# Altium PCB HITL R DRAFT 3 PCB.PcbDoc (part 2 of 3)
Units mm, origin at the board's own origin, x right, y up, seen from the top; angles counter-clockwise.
Board outline 90 x 65 mm, 6 copper layers (L1, L2, L3, L4, L5, L6), stack 1.752 mm thick; 198 components, 194 nets, 830 pads, 458 vias.
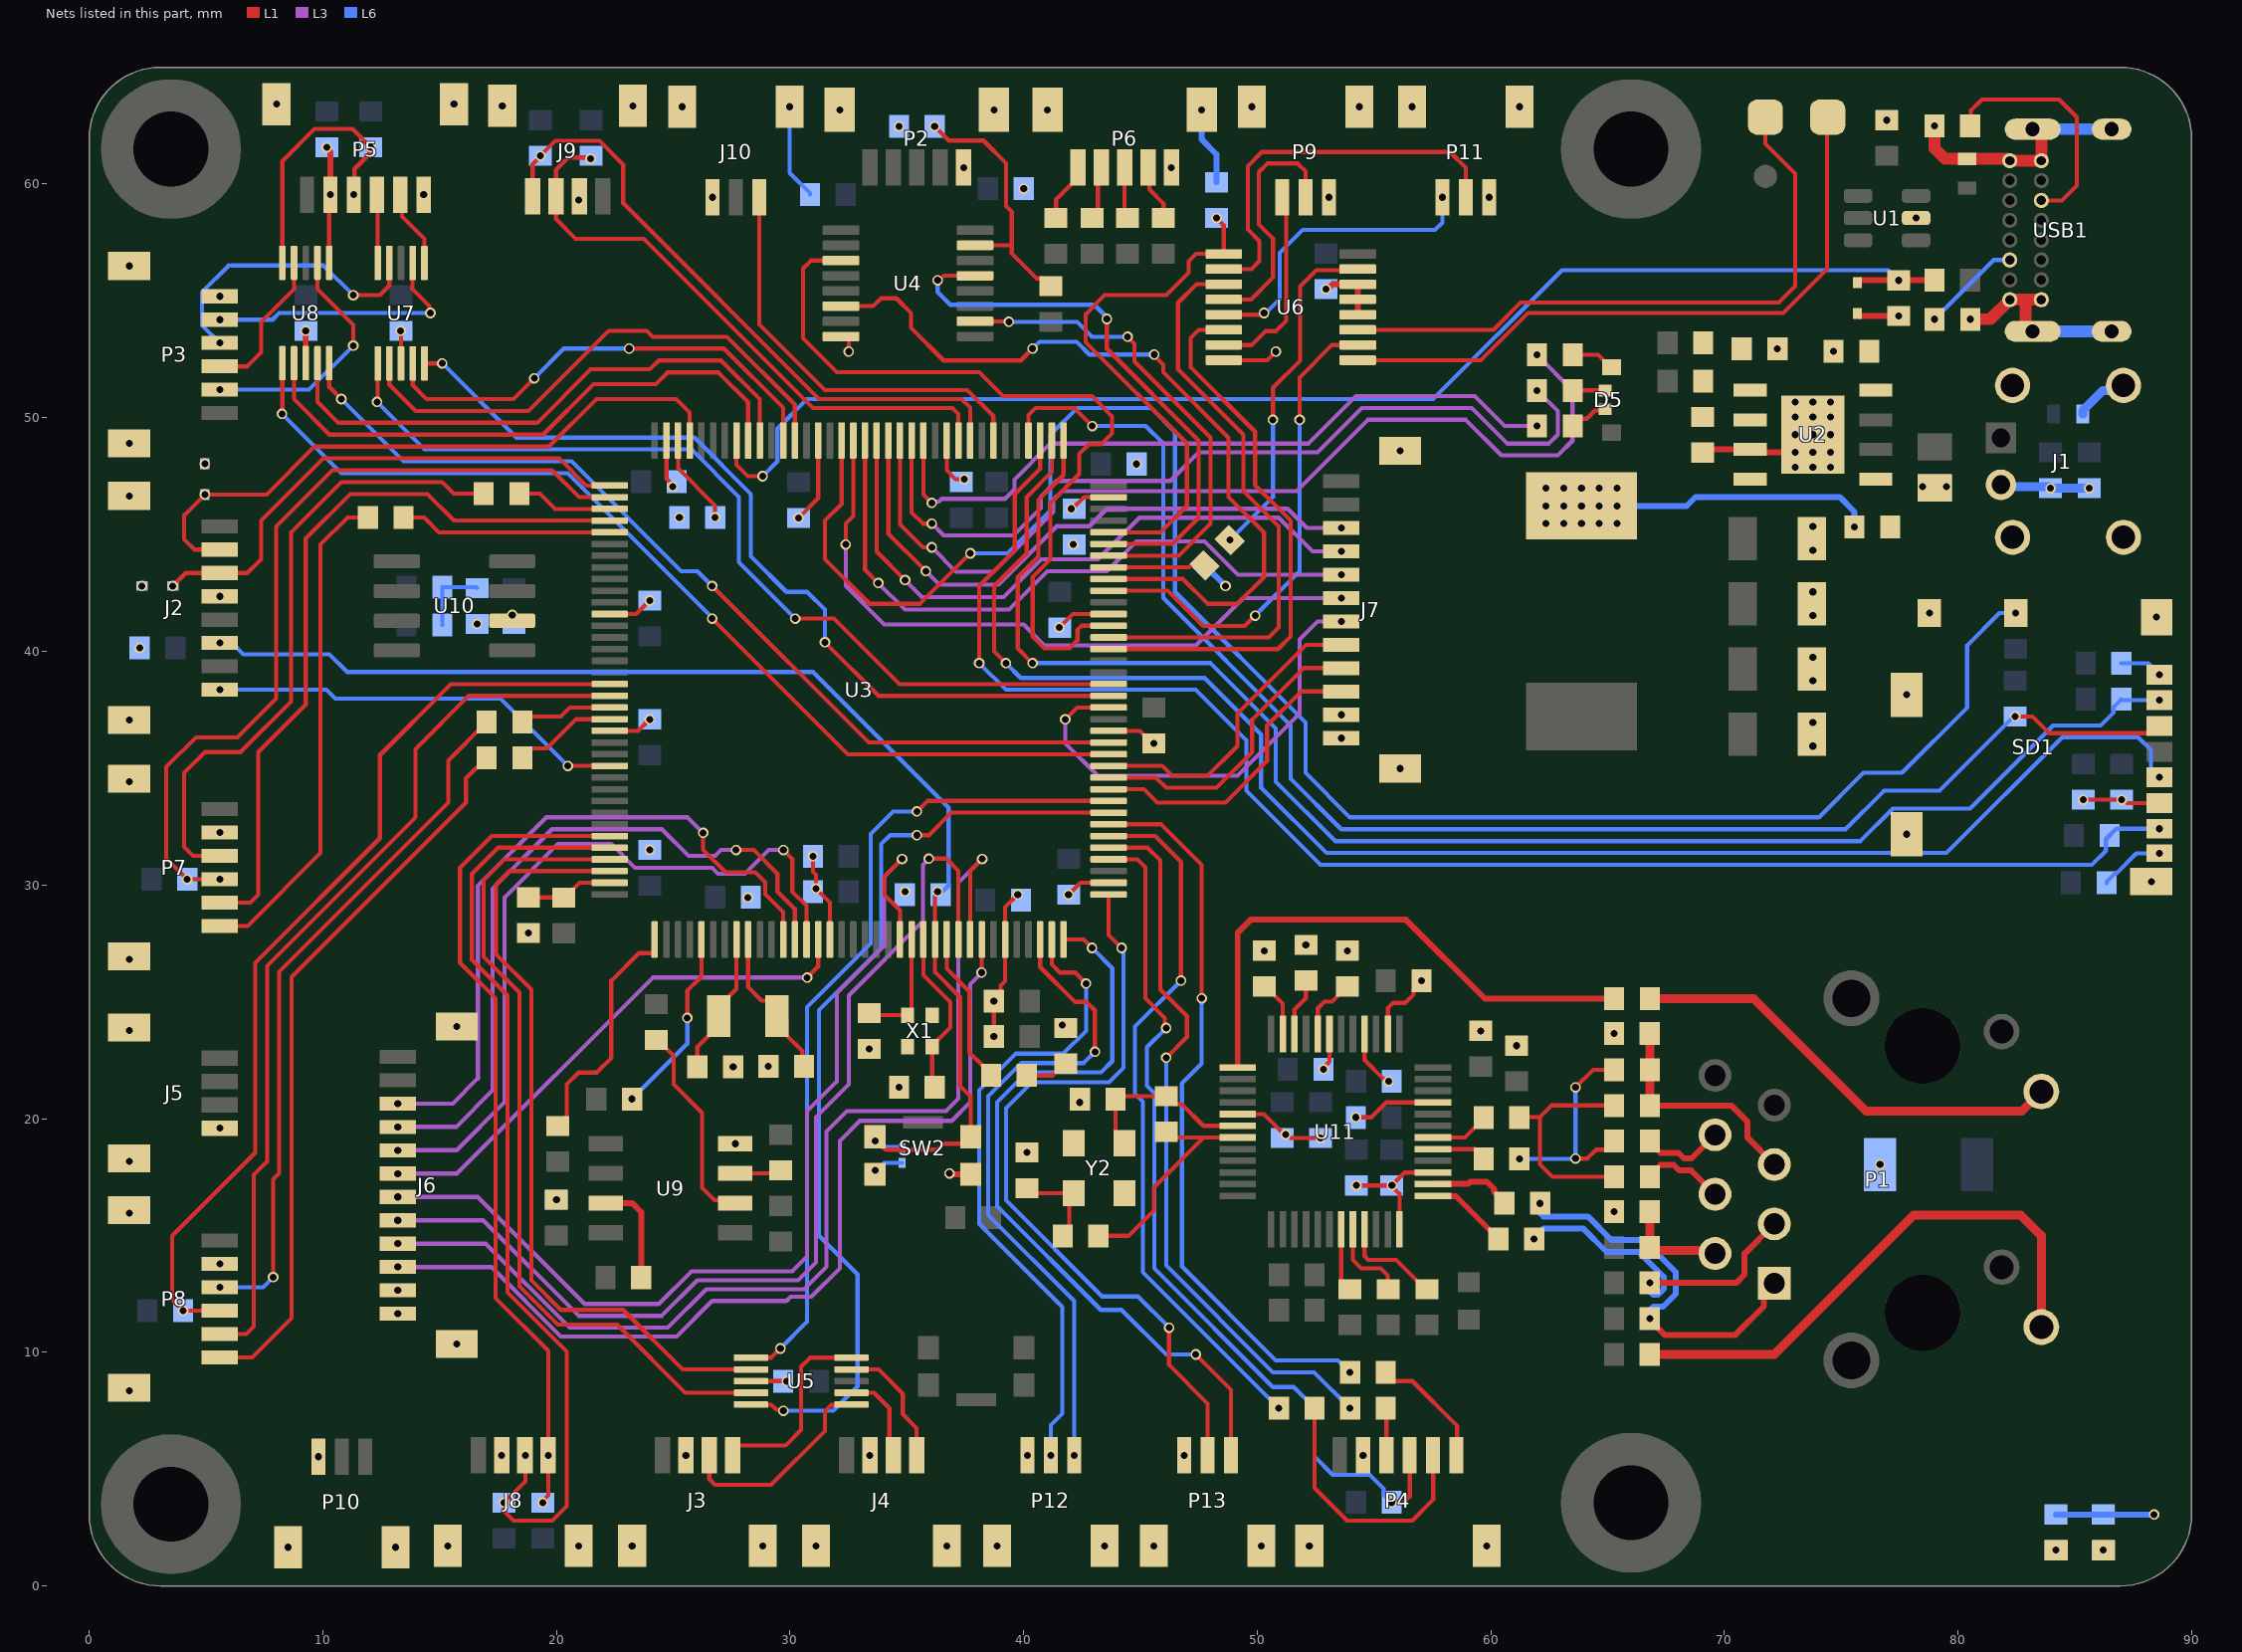
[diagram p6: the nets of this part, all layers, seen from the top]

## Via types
v1: diameter 0.451, hole 0.301, L1 to L6, 453 vias
v2: diameter 0.45, hole 0.3, L1 to L6, 5 vias

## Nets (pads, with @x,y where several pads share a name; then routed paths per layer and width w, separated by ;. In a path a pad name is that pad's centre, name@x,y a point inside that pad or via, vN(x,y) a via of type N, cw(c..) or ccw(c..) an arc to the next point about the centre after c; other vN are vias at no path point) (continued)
GND: C1.1 C2.1 C3.2 C5.1 C6.1 C8.1 C9.1 C10.1 C11.1 C12.1 C13.1 C14.1 C15.1 C16.1 C17.1 C18.1 C19.1 C20.1 C21.1 C22.1 C23.1 C24.1 C25.1 C27.1 C28.1 C29.1 C30.1 C31.1 C32.1 C33.1 C34.1 C35.1 C36.1 C37.2 C38.2 C39.1 C40.1 C41.1 C42.1 C43.1 C44.1 C45.1 C46.1 C47.1 C51.1 C52.1 C53.1 C54.1 C55.1 C56.1 C57.1 C60.1 C61.1 C62.1 C63.1 C64.1 C65.1 C66.1 C67.1 C68.1 D1.2 D2.2 D3.2 D4.2 D6.1 D7.1 J1.2 J1.SH1 J1.SH2 J1.SH3 J1.SH4 J2.4 J2.P1 J2.P2 J3.2 J3.S1 J3.S2 J4.2 J4.S1 J4.S2 J5.4 J5.S1 J5.S2 J6.11 J6.12 J6.S1 J6.S2 J7.11 J7.12 J7.S1 J7.S2 J8.2 J8.S1 J8.S2 J9.2 J9.S1 J9.S2 J10.3 J10.S1 J10.S2 P2.5 P2.6 P2.7 P3.1 P3.S1 P3.S2 P4.2 P4.S1 P4.S2 P5.1 P5.S1 P5.S2 P6.5 P6.6 P6.7 P7.2 P7.S1 P7.S2 P8.2 P8.S1 P8.S2 P9.1 P9.S1 P9.S2 P10.1 P10.S1 P10.S2 P11.1 P11.S1 P11.S2 P12.1 P12.S1 P12.S2 P13.1 P13.S1 P13.S2 R2.1 R3.1 R4.1 R6.1 R7.1 R8.2 R13.2 R18.1 R21.1 R22.1 R23.1 R24.1 R58.1 R59.1 R77.1 R78.1 SD1.6 SD1.10 SD1.G1 SD1.G2 SD1.G3 SD1.G4 SW2.2 SW2.3 U1.2 U2.7 U2.9 U3.16 U3.31 U3.38 U3.51 U3.61 U3.83 U3.94 U3.107 U3.120 U3.130 U4.8 U5.3 U6.8 U6.12 U6.13 U6.14 U7.3 U8.3 U9.4 U10.2 U11.3 U11.9 U11.14 U11.16 U11.19 U11.29 U11.48 USB1.A1 USB1.A12 USB1.B1 USB1.B12 USB1.S1 USB1.S2 USB1.S3 USB1.S4 X1.2 X1.4 Y2.2 Y2.4 | length 108.8
  L1 w0.178: v1(13.335,53.721) 13.343,53.713 13.343,52.332 U7.3@13.351,52.324 ; U3.130@22.279,36.596 23.495,36.596 v1(23.99,37.091) ; U3.120@22.279,41.596 23.415,41.596 v1(23.99,42.171) ; U3.107@24.709,49.026 24.709,47.399 24.976,47.132 v1(24.976,47.058) ; U5.3@28.332,8.761 29.856,8.761 v1(29.858,8.759) ; v1(30.366,45.713) 31.209,46.556 U3.94@31.209,49.026 ; v1(30.981,31.229) 30.981,30.565 31.115,30.431 v1(31.115,29.845) 31.709,29.251 U3.16@31.709,27.666 ; U4.8@32.182,53.478 32.396,53.478 32.512,53.362 v1(32.512,52.832) ; U3.83@36.709,49.026 36.709,47.746 37.084,47.371 v1(37.465,47.371) ; v1(38.728,23.508) v1(38.728,25.032) 39.018,25.322 39.018,25.683 39.209,25.874 39.209,29.049 v1(39.751,29.591) ; v1(41.529,41.021) 42.104,41.596 U3.61@43.639,41.596 ; v1(41.923,29.584) 42.435,30.096 U3.38@43.639,30.096 ; U3.51@43.639,36.596 44.985,36.596 45.52,36.061 v1(45.58,36.061) ; U6.8@48.568,52.459 50.427,52.459 v1(50.8,52.832) ; U11.29@49.164,20.192 50.277,20.192 51.152,19.317 51.289,19.317 51.436,19.17 v1(52.718,19.17) ; v1(52.839,22.111) 52.839,22.185 53.094,22.44 U11.19@53.094,23.622 ; v1(54.222,20.053) 54.88,20.053 55.519,20.692 U11.9@57.524,20.692 ; v1(54.242,17.138) v1(55.766,17.138) ; U11.16@54.594,23.622 54.594,22.513 55.402,21.706 55.437,21.706 55.552,21.59 v1(55.626,21.59) ; U11.14@55.594,23.622 55.594,24.733 55.814,24.953 56.333,24.953 56.689,25.308 56.689,25.554 v1(57.03,25.895) ; U11.48@56.094,15.262 56.094,16.771 55.766,17.099 v1(55.766,17.138) ; U11.3@57.524,17.692 56.32,17.692 v1(55.766,17.138) ; v1(85.357,33.648) v1(87.008,33.648) 87.082,33.648 87.224,33.506 SD1.6@88.624,33.506
  L1 w0.254: U8.3@9.271,52.333 v1(9.271,53.721) ; v1(36.83,17.653) 36.883,17.653 36.921,17.615 SW2.3@37.737,17.615 ; v1(52.946,55.5) 53.02,55.5 53.232,55.712 U6.14@54.305,55.712 U6.13@54.305,55.062 U6.12@54.305,54.412 ; C12.1@69.075,48.507 69.209,48.641 U2.7@71.095,48.641 71.222,48.514 v1(73.025,48.514) ; D3.2@75.692,54.458 75.692,54.422 75.765,54.349 v1(77.457,54.349)
  L1 w0.508: v1(78.987,62.497) 78.987,61.541 79.451,61.077 D1.2@80.391,61.077 82.103,61.077 82.178,61.002 USB1.B1@83.566,61.002 83.566,62.018 83.232,62.352 USB1.S4@83.196,62.352 ; v1(80.525,54.216) 81.38,54.216 USB1.A1@82.216,55.052 82.891,55.052 ; USB1.S3@83.196,53.702 82.891,54.007 82.891,55.052 ; USB1.B12@83.566,55.052 82.891,55.052
  L6 w0.178: v1(29.986,63.311) 29.986,60.478 30.854,59.61 R21.1@30.854,59.55 ; v1(33.655,17.78) 33.705,17.78 34.028,18.103 D4.2@34.798,18.103
  L6 w0.254: v1(47.623,63.182) 47.623,61.908 48.26,61.271 R24.1@48.26,60.077 ; R23.1@47.741,43.68 47.76,43.68 v1(48.641,42.799) ; R77.1@84.188,3.055 R78.1@86.22,3.055 86.227,3.048 v2(88.392,3.048)
  L6 w0.381: J1.2@81.834,47.133 81.909,47.058 83.885,47.058 v1(83.96,46.983) v1(85.611,46.983) ; D2.2@85.334,50.165 85.334,50.29 86.211,51.167 86.868,51.167 J1.SH4@87.084,51.383
  L6 w0.508: USB1.S3@83.196,53.702 USB1.S1@86.576,53.702 ; USB1.S4@83.196,62.352 USB1.S2@86.576,62.352
  other v1: 8.509,1.651 13.109,1.651 15.353,1.713 20.953,1.713 23.243,1.713 28.843,1.713 31.117,1.713 36.717,1.713 38.864,1.713 43.464,1.713 45.579,1.713 50.179,1.713 52.231,1.713 59.831,1.713 9.809,5.526 17.653,5.588 25.543,5.588 33.417,5.588 40.164,5.588 46.879,5.588 54.531,5.588 1.713,8.352 15.736,10.345 13.211,11.645 13.211,12.645 5.588,13.779 1.713,15.952 65.271,16.015 20.005,16.528 76.662,18.034 1.713,18.163 40.145,18.549 27.662,18.923 51.215,19.317 5.588,19.59 42.41,20.693 34.664,21.349 27.566,22.212 29.076,22.238 33.388,22.98 61.1,23.121 65.271,23.635 1.713,23.763 59.576,23.756 15.736,23.945 41.656,24.003 1.713,26.815 50.305,27.185 53.861,27.185 52.083,27.439 18.809,27.941 28.194,29.464 34.925,29.718 88.274,30.146 23.99,31.503 77.799,32.171 5.588,32.242 1.713,34.415 56.122,34.983 73.787,35.941 53.597,36.283 73.787,36.957 1.713,37.054 53.597,37.283 77.799,38.141 73.787,38.735 73.787,39.751 2.16,40.145 16.6,41.175 88.499,41.466 73.787,41.529 18.11,41.563 78.774,41.641 5.588,42.354 73.787,42.545 2.261,42.799 73.787,44.323 42.125,44.577 73.787,45.339 25.266,45.733 1.713,46.654 78.486,47.046 79.502,47.046 73.025,47.879 73.787,47.879 74.549,47.879 4.953,48.031 44.838,48.019 73.787,48.514 74.549,48.514 56.122,48.583 1.713,48.897 73.025,49.276 73.787,49.276 74.549,49.276 73.025,50.038 73.787,50.038 74.549,50.038 73.025,50.673 73.787,50.673 74.549,50.673 74.669,52.845 72.27,52.946 5.588,55.197 1.713,56.497 78.207,58.547 20.955,59.309 26.686,59.436 53.07,59.436 59.927,59.436 14.318,59.548 40.004,59.804 37.433,60.712 46.323,60.712 34.664,62.471 76.949,62.737 32.133,63.182 38.733,63.182 41.023,63.182 25.386,63.311 49.77,63.311 54.37,63.311 56.627,63.311 61.227,63.311 17.684,63.347 23.284,63.347 8.018,63.423 15.618,63.423
GPS_RX_IN: P3.2 U7.7 | length 11.9
  L1 w0.178: U7.7@13.837,56.885 13.837,55.505 14.562,54.78 14.562,54.526 v1(14.605,54.483)
  L6 w0.178: v1(5.588,54.197) 7.842,54.197 8.128,54.483 v1(14.605,54.483)
GPS_RX_OUT: P5.2 U7.6 | length 3.4
  L1 w0.178: P5.2@13.318,59.548 13.399,59.466 13.399,58.61 14.351,57.658 U7.6@14.351,56.624
GPS_RX_SEL: U3.54 U7.5 | length 37.6
  L1 w0.178: U7.5@14.351,52.324 v1(15.113,52.324) ; v1(31.496,40.386) 33.786,38.096 U3.54@43.639,38.096
  L6 w0.178: v1(15.113,52.324) 18.288,49.149 25.908,49.149 28.321,46.736 28.321,44.069 29.845,42.545 30.734,42.545 31.496,41.783 v1(31.496,40.386)
GPS_TX_IN: P3.3 U7.9 | length 12.5
  L1 w0.178: v1(11.303,55.245) 12.446,55.245 12.851,55.65 U7.9@12.851,56.624
  L6 w0.178: v1(5.588,53.197) 4.826,53.959 4.826,55.372 5.969,56.515 ; 6.096,56.515 10.033,56.515 v1(11.303,55.245)
GPS_TX_OUT: P5.3 U7.10 | length 2.9
  L1 w0.178: P5.3@12.318,59.548 12.351,59.514 U7.10@12.351,56.624
GPS_TX_SEL: U3.55 U7.1 | length 39.6
  L1 w0.178: v1(12.319,50.673) 12.351,50.705 U7.1@12.351,52.324 ; v1(30.226,41.402) 31.877,41.402 34.683,38.596 U3.55@43.639,38.596
  L6 w0.178: v1(12.319,50.673) 14.351,48.641 25.781,48.641 27.813,46.609 27.813,43.815 v1(30.226,41.402)
HITL2PDB_GPIO: U3.63 U6.10 | length 21.1
  L1 w0.178: U3.63@43.639,42.596 46.177,42.596 47.692,41.081 49.463,41.081 v1(49.911,41.529) ; v1(51.816,49.911) 51.816,51.723 53.205,53.112 U6.10@54.305,53.112
  L6 w0.178: v1(49.911,41.529) 51.816,43.434 v1(51.816,49.911)
HITL_DSHOT1: U3.60 U4.3 | length 34.6
  L1 w0.178: U4.3@32.182,56.728 30.893,56.728 30.553,56.388 30.553,53.394 32.004,51.943 38.1,51.943 39.116,50.927 42.926,50.927 43.792,50.061 43.792,49.335 43.318,48.861 42.797,48.861 42.385,48.448 42.385,47.592 41.148,46.355 41.148,43.942 40.386,43.18 40.386,40.64 40.894,40.132 41.962,40.132 42.303,40.473 42.303,40.918 42.481,41.096 U3.60@43.639,41.096
HITL_DSHOT2: U3.64 U4.6 | length 34.6
  L1 w0.178: U4.6@32.182,54.778 33.569,54.778 33.902,55.111 34.551,55.111 35.186,54.476 35.186,53.841 36.576,52.451 39.878,52.451 v1(40.386,52.959) ; U3.64@43.639,43.096 46.82,43.096 47.879,42.037 49.149,42.037 50.292,43.18 50.292,45.085 48.768,46.609 48.768,49.149 45.974,51.943 45.974,52.265 45.593,52.646 v1(45.593,52.705)
  L6 w0.178: v1(40.386,52.959) 40.671,53.244 42.279,53.244 42.818,52.705 v1(45.593,52.705)
HITL_DSHOT3: U3.66 U4.10 | length 21.2
  L1 w0.178: U4.10@37.922,54.128 37.935,54.115 39.357,54.115 v1(39.37,54.102) ; U3.66@43.639,44.096 46.636,44.096 48.006,45.466 48.006,49.149 44.749,52.406 44.749,53.168 v1(44.45,53.467)
  L6 w0.178: v1(39.37,54.102) 42.291,54.102 42.926,53.467 v1(44.45,53.467)
HITL_DSHOT4: U3.67 U4.13 | length 24.4
  L1 w0.178: v1(36.322,55.88) 36.396,55.88 36.594,56.078 U4.13@37.922,56.078 ; v1(43.561,54.229) 43.561,52.959 47.498,49.022 47.498,45.72 46.374,44.596 U3.67@43.639,44.596
  L6 w0.178: v1(36.322,55.88) 36.322,55.372 36.859,54.835 43.028,54.835 43.561,54.303 v1(43.561,54.229)
HITL_GPS_RX: U3.97 U7.4 | length 20.4
  L1 w0.178: U7.4@13.851,52.324 13.851,51.392 14.443,50.8 18.161,50.8 v1(19.05,51.689) ; v1(23.114,52.959) 27.178,52.959 29.709,50.428 U3.97@29.709,49.026
  L6 w0.178: v1(19.05,51.689) 20.32,52.959 v1(23.114,52.959)
HITL_GPS_TX: U3.96 U7.2 | length 23
  L1 w0.178: U7.2@12.851,52.324 12.851,51.419 13.978,50.292 18.796,50.292 22.225,53.721 23.876,53.721 24.13,53.467 27.305,53.467 30.209,50.563 U3.96@30.209,49.026
HITL_MAG_SCL: U3.100 U8.2 | length 24.9
  L1 w0.178: U8.2@8.771,52.333 8.771,50.792 10.287,49.276 19.431,49.276 21.59,51.435 24.257,51.435 24.756,51.934 26.933,51.934 28.209,50.658 U3.100@28.209,49.026
HITL_MAG_SDA: U3.99 U8.4 | length 24.5
  L1 w0.178: U8.4@9.771,52.333 9.771,50.681 10.668,49.784 19.177,49.784 21.463,52.07 24.003,52.07 24.384,52.451 27.051,52.451 28.709,50.793 U3.99@28.709,49.026
HITL_PDB_UART_RX: U3.58 U6.6 | length 24.1
  L1 w0.178: U3.58@43.639,40.096 50.891,40.096 51.435,40.64 51.435,45.593 49.911,47.117 49.911,49.403 47.149,52.165 47.149,53.422 47.489,53.762 U6.6@48.565,53.762
HITL_PDB_UART_TX: U3.59 U6.3 | length 25.4
  L1 w0.178: U3.59@43.639,40.596 50.502,40.596 50.927,41.021 50.927,45.339 49.403,46.863 49.403,49.276 46.609,52.07 46.609,54.919 47.402,55.712 U6.3@48.565,55.712
HITL_RF_UART_RX: U3.141 U5.4 | length 35.6
  L1 w0.178: U3.141@22.279,31.096 17.78,31.096 16.891,30.207 16.891,26.924 18.415,25.4 18.415,12.827 20.066,11.176 22.606,11.176 25.519,8.263 U5.4@28.33,8.263
HITL_RF_UART_TX: U3.142 U5.2 | length 33.6
  L1 w0.178: U3.142@22.279,30.596 17.998,30.596 17.422,30.02 17.422,27.028 18.923,25.527 18.923,13.081 20.193,11.811 22.86,11.811 25.408,9.263 U5.2@28.33,9.263
I2C1_SCL: J8.4 R75.1 U3.139 | length 35.8
  L1 w0.178: v1(19.418,3.563) 19.418,3.636 19.653,3.872 v1(19.653,5.588) 19.653,10.065 17.399,12.319 17.399,25.146 15.875,26.67 15.875,30.734 17.237,32.096 U3.139@22.279,32.096
I2C1_SDA: J8.3 R73.1 U3.140 | length 41
  L1 w0.178: v1(18.669,5.588) 18.669,4.465 v1(17.767,3.563) 17.767,3.188 18.161,2.794 19.831,2.794 20.447,3.41 20.447,10.033 17.907,12.573 17.907,25.273 16.383,26.797 16.383,30.48 17.499,31.596 U3.140@22.279,31.596
I2C4_SCL: J9.4 R76.1 U3.81 | length 27.6
  L1 w0.178: J9.4@18.984,59.472 18.984,60.845 19.317,61.179 v1(19.317,61.207) 19.959,61.849 21.844,61.849 22.86,60.833 22.86,59.182 31.242,50.8 37.338,50.8 37.709,50.429 U3.81@37.709,49.026
I2C4_SDA: J9.3 R74.1 U3.82 | length 25.7
  L1 w0.178: v1(21.463,61.087) 21.411,61.139 20.499,61.139 19.984,60.624 J9.3@19.984,59.472 19.984,58.502 20.828,57.658 23.749,57.658 30.988,50.419 36.957,50.419 37.209,50.167 U3.82@37.209,49.026
LED: D8.2 U3.26 | length 6.6
  L1 w0.178: U3.26@36.709,27.666 36.709,26.41 37.676,25.443 37.676,22.832 38.262,22.245 38.264,22.245 38.605,21.904 D8.2@38.605,21.844
LINKLED: R57.2 U11.25 | length 23.5
  L1 w0.254: U11.25@49.164,22.192 49.164,27.955 49.724,28.515 56.368,28.515 59.75,25.133 R57.2@65.279,25.133
MAG_SCL_IN: P3.4 U8.9 | length 6.4
  L1 w0.178: P3.4@5.588,52.197 6.769,52.197 7.369,52.797 7.369,54.105 8.771,55.507 U8.9@8.771,56.633
MAG_SCL_OUT: P5.4 R25.2 U8.10 | length 11.4
  L1 w0.178: U8.10@8.271,56.633 8.271,60.976 9.652,62.357 11.274,62.357 v1(12.05,61.58)
  L1 w0.203: v1(11.318,59.548) 11.359,59.589 11.359,60.645 12.003,61.289 12.003,61.533 v1(12.05,61.58)
MAG_SCL_SEL: U3.49 U8.1 | length 43.6
  L1 w0.178: v1(8.255,50.165) 8.271,50.181 U8.1@8.271,52.333 ; v1(26.67,41.402) 32.476,35.596 U3.49@43.639,35.596
  L6 w0.178: v1(8.255,50.165) 10.795,47.625 20.488,47.625 26.67,41.443 v1(26.67,41.402)
MAG_SDA_IN: P3.5 U8.7 | length 10.6
  L1 w0.178: U8.7@9.771,56.633 9.771,55.507 11.303,53.975 v1(11.303,53.086)
  L6 w0.178: v1@5.715,51.197 9.414,51.197 v1(11.303,53.086)
  other v1: 5.588,51.197
MAG_SDA_OUT: P5.5 R26.1 U8.6 | length 5
  L1 w0.178: U8.6@10.271,56.633 10.271,59.501 v1(10.318,59.548)
  L1 w0.254: v1(10.172,61.573) 10.172,61.52 10.318,61.374 v1(10.318,59.548)
MAG_SDA_SEL: U3.50 U8.5 | length 40.7
  L1 w0.178: U8.5@10.271,52.333 10.271,51.324 v1(10.795,50.8) ; v1(26.67,42.799) 33.373,36.096 U3.50@43.639,36.096
  L6 w0.178: v1(10.795,50.8) 13.462,48.133 20.647,48.133 25.346,43.434 26.035,43.434 v1(26.67,42.799)
NetC4_1: C4.1 U2.1
NetC4_2: C4.2 L1.2 U2.8 | length 11.2
  L6 w0.254: v1(65.405,46.228) 68.387,46.228 68.768,46.609 74.93,46.609 75.566,45.973 v1(75.566,45.326)
  other v1: 62.357,45.466 63.119,45.466 63.881,45.466 64.643,45.466 65.405,45.466 62.357,46.228 63.119,46.228 63.881,46.228 64.643,46.228 62.357,46.99 63.119,46.99 63.881,46.99 64.643,46.99 65.405,46.99
NetC7_1: C7.1 R5.1 R7.2 U2.5
NetC12_2: C12.2 U2.6
NetC29_2: C29.2 U3.106 | length 4
  L1 w0.178: U3.106@25.209,49.026 25.209,47.831 26.796,46.244 v1(26.796,45.733)
NetC36_2: C36.2 U3.71 | length 1.8
  L1 w0.178: v1(42.037,46.101) 42.09,46.101 42.585,46.596 U3.71@43.639,46.596
NetC47_2: C47.2 R37.2 R38.1 | length 3.1
  L6 w0.178: R37.2@15.112,41.135 R38.1@15.112,42.753 16.552,42.753 C47.2@16.6,42.705
NetC60_2: C60.2 P1.2 R47.2 | length 4.4
  L1 w0.381: C60.2@66.801,16.015 R47.2@66.801,14.491 66.935,14.358 69.462,14.358 P1.2@69.596,14.224
NetC63_2: C63.2 R53.1 Y2.3 | length 4.1
  L1 w0.178: C63.2@40.145,17.019 40.354,16.81 Y2.3@42.143,16.81 41.956,16.622 41.956,15.262 R53.1@41.674,14.98
NetC64_2: C64.2 R50.1 U11.30 Y2.1 | length 7.9
  L1 w0.178: Y2.1@44.318,18.943 43.941,19.321 C64.2@43.941,20.841 44.062,20.962 R50.1@46.114,20.962 46.455,20.621 46.765,20.621 47.694,19.692 U11.30@49.164,19.692
NetC65_2: C65.2 P1.5 R55.1 R56.1 | length 9.9
  L1 w0.254: R56.1@66.809,20.561 70.293,20.561 70.993,19.861 70.993,19.177 P1.5@72.136,18.034
  L1 w0.381: C65.2@66.801,23.635 66.805,23.631 66.805,22.089 R55.1@66.809,22.085 R56.1@66.809,20.561
NetC67_2: C67.2 U11.20 | length 2.6
  L1 w0.178: U11.20@52.594,23.622 52.594,24.716 52.879,25.001 53.207,25.001 C67.2@53.734,25.528
NetC68_2: C68.2 U11.22 | length 2.5
  L1 w0.178: U11.22@51.594,23.622 51.594,24.67 52.083,25.159 C68.2@52.083,25.909
NetD5_B: D5.B R14.1 | length 1.7
  L1 w0.178: R14.1@63.507,49.644 63.819,49.956 64.099,49.956 64.458,50.315 64.848,50.315 D5.B@64.895,50.362
NetD5_G: D5.G R16.1 | length 1.4
  L1 w0.178: R16.1@63.507,51.168 D5.G@64.89,51.168
NetD5_R: D5.R R17.1 | length 1.9
  L1 w0.178: R17.1@63.507,52.692 64.591,52.692 65.12,52.162 D5.R@65.17,52.162
NetD8_1: D8.1 R18.2 | length 1.9
  L1 w0.178: D8.1@40.135,21.844 41.227,21.844 41.736,22.353 R18.2@41.796,22.353
NetD9_1: D9.1 R77.2
  other v2: 84.188,1.525
NetD10_1: D10.1 R78.2
  other v2: 86.22,1.525
NetP1_9: P1.9 R54.1 | length 23.5
  L1 w0.381: R54.1@66.802,9.906 72.136,9.906 78.105,15.875 82.677,15.875 83.566,14.986 P1.9@83.566,11.074
NetP1_11: P1.11 R57.1 | length 19.1
  L1 w0.381: R57.1@66.809,25.133 71.26,25.133 76.073,20.32 82.729,20.32 P1.11@83.566,21.157
NetP4_3: P4.3 R61.1 | length 2
  L1 w0.178: R61.1@55.506,7.607 55.531,7.582 P4.3@55.531,5.588
NetP4_6: P4.6 R62.1 | length 5.3
  L1 w0.178: R62.1@55.506,9.131 55.506,9.104 55.847,8.763 56.642,8.763 58.554,6.851 58.554,5.611 P4.6@58.531,5.588
NetP6_1: P6.1 R63.2 | length 2.6
  L1 w0.178: R63.2@41.389,58.546 41.389,59.333 42.323,60.267 P6.1@42.323,60.712
NetP6_2: P6.2 R64.1 | length 2.3
  L1 w0.178: R64.1@42.939,58.554 43.18,58.795 43.18,60.569 P6.2@43.323,60.712
NetP6_3: P6.3 R65.2 | length 2.2
  L1 w0.178: P6.3@44.323,60.712 44.323,58.66 R65.2@44.437,58.546
NetP6_4: P6.4 R66.1 | length 2.4
  L1 w0.178: P6.4@45.323,60.712 45.381,60.653 45.381,59.775 45.987,59.169 R66.1@45.987,58.554
NetP7_3: P7.3 R68.1 | length 27.3
  L1 w0.178: P7.3@5.588,31.242 4.445,31.242 4.064,31.623 4.064,34.798 4.953,35.687 6.477,35.687 8.636,37.846 8.636,45.085 10.795,47.244 15.113,47.244 15.608,46.749 R68.1@16.884,46.749
NetP7_6: P7.6 R69.1 | length 21.3
  L1 w0.178: P7.6@5.588,28.242 5.593,28.247 6.784,28.247 9.906,31.369 9.906,44.577 11.062,45.733 R69.1@11.931,45.733
NetP8_3: P8.3 R71.1 | length 30
  L1 w0.178: v1(7.874,13.208) 7.874,17.399 8.128,17.653 8.128,26.289 15.367,33.528 15.367,35.326 R71.1@17.011,36.97
  L6 w0.178: v1(5.588,12.779) 7.445,12.779 v1(7.874,13.208)
NetP8_6: P8.6 R72.1 | length 31.2
  L1 w0.178: P8.6@5.588,9.779 6.985,9.779 8.66,11.454 8.66,26.059 16.129,33.528 16.129,34.564 R72.1@17.011,35.446
NetR2_2: R2.2 USB1.B5 | length 10.4
  L1 w0.178: R2.2@80.517,62.497 80.549,62.529 80.549,63.15 81.026,63.627 84.328,63.627 85.09,62.865 85.09,59.944 84.448,59.302 USB1.B5@83.566,59.302
NetR3_2: R3.2 USB1.A5 | length 4.3
  L6 w0.178: v1(78.995,54.216) 81.531,56.752 USB1.A5@82.216,56.752
NetR6_2: R6.2 U2.4
NetR8_1: R8.1 R9.2 U3.143 | length 3.7
  L1 w0.178: R8.1@18.809,29.471 20.299,29.471 R9.2@20.307,29.463 20.367,29.463 21,30.096 U3.143@22.279,30.096
NetR10_2: R10.2 U3.1 | length 10.6
  L1 w0.178: R10.2@20.053,19.684 20.106,19.684 20.447,20.025 20.447,21.463 20.955,21.971 21.717,21.971 22.352,22.606 22.352,25.908 23.525,27.081 24.158,27.081 24.209,27.133 U3.1@24.209,27.666
NetR11_2: R11.2 U3.5 | length 8.1
  L1 w0.178: v1(25.605,24.31) 25.605,25.478 26.209,26.082 U3.5@26.209,27.666
  L6 w0.178: v1(23.24,20.841) 25.605,23.206 v1(25.605,24.31)
NetR15_2: R15.2 U3.42 | length 30.3
  L1 w0.178: U3.42@43.639,32.096 45.628,32.096 46.736,30.988 v1(46.736,25.908)
  L6 w0.178: v1(46.736,25.908) 44.764,23.936 44.764,21.073 45.108,20.729 45.108,13.427 v1(50.928,7.607)
NetR19_1: R19.1 R22.2 U4.15 | length 11.5
  L1 w0.178: v1(36.194,62.471) 36.802,61.864 38.28,61.864 39.249,60.895 39.249,59.055 39.497,58.807 39.497,57.378 ; U4.15@37.922,57.378 39.497,57.378 ; R19.1@41.161,55.633 40.827,55.967 40.553,55.967 39.497,57.023 39.497,57.378
NetR20_1: R20.1 R23.2 U6.15 | length 14.9
  L1 w0.178: v1(50.673,49.911) 50.673,51.276 51.842,52.445 51.842,55.624 52.531,56.313 54.256,56.313 U6.15@54.305,56.362
  L6 w0.178: v1(48.828,44.768) R23.2@48.876,44.72 ; R23.2@48.876,44.812 50.673,46.609 v1(50.673,49.911)
NetR27_2: R27.2 SD1.1 | length 1.8
  L6 w0.178: R27.2@86.994,39.484 88.147,39.484 v1(88.624,39.006)
NetR31_2: R31.2 U9.2 | length 8.9
  L1 w0.178: R31.2@24.27,23.369 24.33,23.369 25.019,22.68 25.019,21.463 26.239,20.243 26.239,17.032 26.764,16.507 27.538,16.507 U9.2@27.662,16.383
NetR32_1: R32.1 U9.7 | length 4.5
  L1 w0.254: U9.7@22.122,16.383 23.241,16.383 23.629,15.995 R32.1@23.629,13.195
NetR34_2: R34.2 U9.3 | length 2
  L1 w0.178: U9.3@27.662,17.653 29.476,17.653 R34.2@29.604,17.781
NetR35_2: R35.2 SD1.8 | length 2.8
  L6 w0.178: R35.2@86.359,30.086 86.359,30.146 86.7,30.487 86.76,30.487 87.63,31.356 v1(88.624,31.356)
NetR40_2: R40.2 U11.43 | length 2.7
  L1 w0.178: U11.43@53.594,15.262 53.594,13.04 53.935,12.699 R40.2@53.962,12.699
NetR41_2: R41.2 U11.44 | length 3.7
  L1 w0.178: U11.44@54.094,15.262 54.094,13.951 54.456,13.589 55.283,13.589 55.58,13.292 55.58,12.732 R41.2@55.613,12.699
NetR42_2: R42.2 U11.45 | length 4.4
  L1 w0.178: U11.45@54.594,15.262 54.594,14.113 54.753,13.954 55.949,13.954 57.204,12.699 R42.2@57.264,12.699
NetR50_2: R50.2 R53.2 U11.31 | length 10
  L1 w0.178: R53.2@43.204,14.98 44.493,14.98 45.57,16.058 45.57,17.05 47.712,19.192 ; R50.2@46.114,19.432 46.354,19.192 U11.31@49.164,19.192
NetR59_2: R59.2 U11.23 | length 2.4
  L1 w0.178: R59.2@50.305,25.655 50.365,25.655 51.094,24.926 U11.23@51.094,23.622
NRST: C35.2 D4.1 J2.6 SW2.1 SW2.4 U3.25 | length 55.4
  L1 w0.178: SW2.1@33.712,19.09 33.637,19.165 SW2.1@33.637,19.215 33.655,19.197 v1(33.655,19.05) 33.752,19.05 33.998,18.804 33.998,18.773 34.102,18.669 36.322,18.669 36.576,18.923 37.445,18.923 SW2.4@37.737,19.215 ; v1(36.322,29.718) 36.322,29.644 36.209,29.531 U3.25@36.209,27.666 36.209,26.275 37.276,25.208 37.276,21.398 37.737,20.937 SW2.4@37.737,19.165
  L6 w0.178: v1(5.588,40.354) 6.128,40.354 6.604,39.878 10.287,39.878 11.049,39.116 30.988,39.116 36.789,33.315 36.789,29.979 36.528,29.718 v1(36.322,29.718) ; v1(33.655,19.05) 33.915,18.79 34.737,18.79 34.798,18.729 D4.1@34.798,18.727
PB0: J7.10 U3.46 | length 13.1
  L1 w0.178: U3.46@43.639,34.096 45.152,34.096 45.72,33.528 48.641,33.528 50.419,35.306 50.419,36.83 51.872,38.283 J7.10@53.597,38.283
PB1: J7.9 U3.47 | length 13.1
  L1 w0.178: U3.47@43.639,34.596 45.668,34.596 46.101,34.163 48.26,34.163 49.784,35.687 49.784,37.084 51.983,39.283 J7.9@53.597,39.283
PB2: J7.8 U3.48 | length 13.3
  L1 w0.178: U3.48@43.639,35.096 45.93,35.096 46.355,34.671 47.879,34.671 49.149,35.941 49.149,37.338 52.094,40.283 J7.8@53.597,40.283
PC1: J6.8 U3.27 | length 44.3
  L1 w0.178: v1(35.945,31.127) 36.691,31.127 37.209,30.609 U3.27@37.209,27.666
  L3 w0.178: v1(13.211,15.645) 16.867,15.645 20.955,11.557 24.511,11.557 26.035,13.081 30.353,13.081 31.115,13.843 31.115,20.066 32.512,21.463 32.512,25.273 35.687,28.448 35.687,30.869 v1(35.945,31.127)
PC2_C: J6.9 U3.28 | length 47.3
  L1 w0.178: U3.28@37.709,27.666 37.709,30.597 v1(38.227,31.115)
  L3 w0.178: v1(13.211,14.645) 16.978,14.645 20.574,11.049 24.765,11.049 26.416,12.7 30.607,12.7 31.559,13.652 31.559,19.45 32.43,20.32 36.68,20.32 37.211,20.851 37.211,30.099 v1(38.227,31.115)
PC3_C: J6.10 U3.29 | length 40.3
  L1 w0.178: v1(38.2,26.251) 38.209,26.26 U3.29@38.209,27.666
  L3 w0.178: v1(13.211,13.645) 17.216,13.645 20.193,10.668 25.146,10.668 26.67,12.192 29.845,12.192 30.023,12.37 30.912,12.37 32.131,13.589 32.131,19.05 32.983,19.902 36.92,19.902 37.719,20.701 37.719,25.757 38.2,26.238 v1(38.2,26.251)
PC14_OSC32_IN: C32.2 U3.8 Y1.1 | length 6.1
  L1 w0.178: C32.2@26.036,22.212 26.036,23.076 26.944,23.984 Y1.1@26.944,24.384 26.944,24.784 27.709,25.549 U3.8@27.709,27.666
PC15_OSC32_OUT: C33.2 U3.9 Y1.2 | length 6.6
  L1 w0.178: U3.9@28.209,27.666 28.209,25.619 28.781,25.047 29.033,25.047 29.855,24.224 29.855,23.563 30.527,22.891 30.527,22.317 C33.2@30.606,22.238
PDB_DISCONNECT: R20.2 U3.65 | length 4.2
  L1 w0.178: U3.65@43.639,43.596 47.089,43.596 47.222,43.728 47.704,43.728 R20.2@47.746,43.686
PDB_GPIO_IN: TP3.1 U6.9 | length 28.2
  L1 w0.178: U6.9@54.305,52.462 59.574,52.462 61.595,54.483 72.517,54.483 74.398,56.364 TP3.1@74.398,62.841
PDB_GPIO_OUT: TP4.1 U6.11 | length 27.3
  L1 w0.178: U6.11@54.305,53.762 60.112,53.762 61.277,54.927 72.326,54.927 73.025,55.626 73.025,60.452 71.755,61.722 TP4.1@71.755,62.865
PDB_RX_IN: P9.3 U6.7 | length 8.5
  L1 w0.178: U6.7@48.565,53.112 49.763,53.112 50.359,53.709 50.803,53.709 51.236,54.142 51.236,59.27 P9.3@51.07,59.436
PDB_RX_OUT: P11.3 U6.5 | length 13.2
  L1 w0.178: U6.5@48.565,54.412 50.147,54.412 50.218,54.483 v1(50.292,54.483)
  L6 w0.178: v1(50.292,54.483) 50.366,54.483 50.96,55.077 50.96,57.056 51.938,58.034 57.613,58.034 57.927,58.348 v1(57.927,59.436)
PDB_SEL: R24.2 U3.68 U6.1 | length 22.7
  L1 w0.178: U3.68@43.639,45.096 45.858,45.096 46.99,46.228 46.99,48.895 42.651,53.234 42.651,54.426 43.469,55.245 46.101,55.245 47.066,56.21 47.066,56.694 47.384,57.012 U6.1@48.565,57.012 48.565,58.242 v1(48.26,58.547)
PDB_TX_IN: P9.2 U6.4 | length 10.7
  L1 w0.178: U6.4@48.565,55.062 49.738,55.062 50.673,55.997 50.673,57.676 50.071,58.278 50.071,60.522 50.43,60.881 51.738,60.881 52.07,60.549 P9.2@52.07,59.436
PDB_TX_OUT: P11.2 U6.2 | length 17.1
  L1 w0.178: U6.2@48.565,56.362 49.746,56.362 50.092,56.709 50.092,57.561 49.595,58.059 49.595,60.771 50.199,61.375 58.259,61.375 58.927,60.707 P11.2@58.927,59.436
PF2: J6.3 U3.12 | length 30
  L1 w0.178: v1(26.283,32.229) 26.283,31.502 27.246,30.539 28.516,30.539 28.945,30.11 28.945,29.602 29.709,28.838 U3.12@29.709,27.666
  L3 w0.178: v1(13.211,20.645) 15.565,20.645 16.637,21.717 16.637,29.972 19.558,32.893 25.619,32.893 v1(26.283,32.229)
PF3: J6.4 U3.13 | length 30.7
  L1 w0.178: v1(27.686,31.496) 28.448,31.496 29.464,30.48 29.464,29.718 30.209,28.973 U3.13@30.209,27.666
  L3 w0.178: v1(13.211,19.645) 15.708,19.645 17.272,21.209 17.272,29.845 19.812,32.385 24.511,32.385 25.654,31.242 26.797,31.242 27.051,31.496 v1(27.686,31.496)
PF4: J6.5 U3.14 | length 32.3
  L1 w0.178: v1(29.718,31.496) 30.099,31.115 30.099,29.718 30.709,29.108 U3.14@30.709,27.666
  L3 w0.178: v1(13.211,18.645) 15.724,18.645 17.78,20.701 17.78,29.464 20.066,31.75 22.352,31.75 23.368,30.734 26.67,30.734 26.924,30.48 28.067,30.48 29.083,31.496 v1(29.718,31.496)
PF5: J6.6 U3.15 | length 22.8
  L1 w0.178: v1(30.734,26.035) 31.209,26.51 U3.15@31.209,27.666
  L3 w0.178: v1(13.211,17.645) 15.74,17.645 24.13,26.035 v1(30.734,26.035)
PF10: J6.7 U3.22 | length 43
  L1 w0.178: U3.22@34.709,27.666 34.709,28.913 34.036,29.586 34.036,30.353 v1(34.798,31.115)
  L3 w0.178: v1(13.211,16.645) 16.629,16.645 21.209,12.065 24.384,12.065 25.781,13.462 30.099,13.462 30.734,14.097 30.734,20.32 32.004,21.59 32.004,25.363 34.036,27.395 34.036,30.353 v1(34.798,31.115)
PF13: J7.7 U3.53 | length 20.1
  L1 w0.178: v1(41.783,37.084) 42.295,37.596 U3.53@43.639,37.596
  L3 w0.178: v1(41.783,37.084) 41.783,36.068 43.18,34.671 49.149,34.671 51.816,37.338 51.816,40.513 52.586,41.283 v1(53.597,41.283)
PG3: J7.3 U3.88 | length 26
  L1 w0.178: U3.88@34.209,49.026 34.209,45.039 v1(35.814,43.434)
  L3 w0.178: v1(35.814,43.434) 36.389,42.859 38.922,42.859 41.419,45.356 42.816,45.356 43.561,46.101 51.308,46.101 52.126,45.283 v1(53.597,45.283)
PG4: J7.4 U3.89 | length 27.5
  L1 w0.178: U3.89@33.709,49.026 33.709,44.269 v1(34.925,43.053)
  L3 w0.178: v1(34.925,43.053) 35.656,42.322 39.147,42.322 40.767,43.942 43.18,43.942 44.958,45.72 50.927,45.72 52.364,44.283 v1(53.597,44.283)
PG5: J7.5 U3.90 | length 28.4
  L1 w0.178: U3.90@33.209,49.026 33.209,43.499 v1(33.782,42.926)
  L3 w0.178: v1(33.782,42.926) 34.925,41.783 39.37,41.783 41.021,43.434 43.561,43.434 44.831,44.704 47.752,44.704 49.173,43.283 v1(53.597,43.283)
PG6: J7.6 U3.91 | length 29.5
  L1 w0.178: v1(32.385,44.577) 32.385,45.466 32.709,45.79 U3.91@32.709,49.026
  L3 w0.178: v1(32.385,44.577) 32.385,42.799 34.036,41.148 40.005,41.148 40.894,40.259 47.374,40.259 49.398,42.283 v1(53.597,42.283)
PH0_OSC_IN: C30.2 U3.23 X1.1 | length 5
  L1 w0.178: C30.2@33.388,24.51 33.474,24.424 X1.1@35.035,24.424 35.209,24.598 U3.23@35.209,27.666
PH1_OSC_OUT: C31.2 U3.24 X1.3 | length 7.1
  L1 w0.178: U3.24@35.709,27.666 35.709,26.14 36.857,24.992 36.857,23.897 X1.3@36.085,23.125 ; X1.3@36.085,23.074 36.085,21.458 C31.2@36.194,21.349
RF_RX_IN: J3.3 U5.6 | length 9.1
  L1 w0.178: J3.3@26.543,5.588 26.543,4.572 26.797,4.318 29.185,4.318 31.496,6.629 31.496,7.469 31.772,7.745 32.612,7.745 U5.6@32.63,7.763
RF_RX_OUT: J4.3 U5.7 | length 4
  L1 w0.178: U5.7@32.63,8.263 33.593,8.263 34.256,7.6 34.256,5.749 J4.3@34.417,5.588
RF_RX_SEL: U3.44 U5.5 | length 40.4
  L1 w0.178: U5.5@28.33,7.763 28.336,7.757 29.2,7.757 29.421,7.536 29.675,7.536 v1(29.718,7.493) ; v1(35.433,32.131) 35.941,32.131 36.906,33.096 U3.44@43.639,33.096
  L6 w0.178: v1(29.718,7.493) 31.849,7.493 32.893,8.537 32.893,13.335 31.242,14.986 31.242,24.638 33.909,27.305 33.909,31.75 34.29,32.131 v1(35.433,32.131)
RF_TX_IN: J3.4 U5.10 | length 8.5
  L1 w0.178: J3.4@27.543,5.588 27.543,5.761 27.784,6.002 29.806,6.002 30.48,6.677 30.48,9.382 30.861,9.763 U5.10@32.63,9.763
RF_TX_OUT: J4.4 U5.9 | length 5.5
  L1 w0.178: U5.9@32.63,9.263 33.79,9.263 34.831,8.222 34.831,7.343 35.417,6.757 J4.4@35.417,5.588
RF_TX_SEL: U3.45 U5.1 | length 35.8
  L1 w0.178: U5.1@28.33,9.763 28.336,9.769 29.2,9.769 v1(29.591,10.16) ; v1(35.433,33.147) 35.882,33.596 U3.45@43.639,33.596
  L6 w0.178: v1(29.591,10.16) 30.734,11.303 30.734,24.765 33.458,27.489 33.458,32.188 34.417,33.147 v1(35.433,33.147)
RGB_B: R14.2 U3.85 | length 31.4
  L1 w0.178: U3.85@35.709,49.026 35.709,46.714 v1(36.068,46.355)
  L3 w0.178: v1(36.068,46.355) 36.12,46.407 36.374,46.407 36.494,46.527 39.2,46.527 39.607,46.935 39.607,47.354 41.148,48.895 52.197,48.895 54.229,50.927 59.309,50.927 60.592,49.644 v1(61.977,49.644)
RGB_G: R16.2 U3.86 | length 36.7
  L1 w0.178: U3.86@35.209,49.026 35.209,45.944 35.687,45.466 v1(36.068,45.466)
  L3 w0.178: v1(36.068,45.466) 36.576,44.958 39.566,44.958 40.743,46.134 40.743,46.628 41.408,47.294 46.278,47.294 47.498,48.514 52.578,48.514 54.483,50.419 59.182,50.419 60.706,48.895 62.484,48.895 62.865,49.276 62.865,50.28 v1(61.977,51.168)
RGB_R: R17.2 U3.87 | length 41.4
  L1 w0.178: U3.87@34.709,49.026 34.709,45.428 35.687,44.45 v1(36.068,44.45)
  L3 w0.178: v1(36.068,44.45) 37.106,43.412 38.713,43.412 41.262,45.961 41.262,46.467 41.658,46.863 51.689,46.863 54.737,49.911 58.928,49.911 60.452,48.387 62.865,48.387 63.5,49.022 63.5,51.169 v1(61.977,52.692)
RX2_N: C59.2 R51.1 R55.2 | length 9.4
  L1 w0.178: v1(63.627,18.288) 64.135,18.288 64.516,18.669 64.938,18.669 65.279,19.01 C59.2@65.279,19.037 ; v1(63.627,21.336) 64.376,22.085 R55.2@65.279,22.085
  L6 w0.178: v1(61.221,18.275) 61.227,18.281 63.62,18.281 v1(63.627,18.288) v1(63.627,21.336)
RX2_P: C58.2 R52.1 R56.2 | length 9.7
  L1 w0.178: R52.1@61.221,20.053 61.236,20.068 62.105,20.068 ; C58.2@65.279,17.513 62.629,17.513 62.105,18.037 62.105,20.068 ; R56.2@65.279,20.561 62.598,20.561 62.105,20.068
RX3_N: C59.1 P1.6 | length 3.6
  L1 w0.254: C59.1@66.809,19.037 66.809,18.977 67.257,18.529 68.038,18.529 68.279,18.288 68.58,18.288 P1.6@69.596,19.304
RX3_P: C58.1 P1.4 | length 3.6
  L1 w0.254: C58.1@66.809,17.513 66.809,17.573 67.257,18.021 67.828,18.021 68.069,17.78 68.58,17.78 P1.4@69.596,16.764
RX_N: R51.2 U11.5 | length 2.4
  L1 w0.178: U11.5@57.524,18.692 59.334,18.692 59.691,18.335 R51.2@59.691,18.275
RX_P: R52.2 U11.6 | length 2.6
  L1 w0.178: U11.6@57.524,19.192 58.89,19.192 59.691,19.993 R52.2@59.691,20.053
SD_CLK: SD1.5 U3.74 | length 68.1
  L1 w0.178: v1(39.243,39.497) 38.735,40.005 38.735,42.799 40.132,44.196 40.132,46.609 41.209,47.686 U3.74@41.209,49.026
  L6 w0.178: v1(39.243,39.497) 39.878,38.862 47.752,38.862 50.165,36.449 50.165,34.163 52.959,31.369 79.502,31.369 84.455,36.322 87.717,36.322 88.265,35.774 88.265,34.966 v1(88.624,34.606)
SD_CMD: R30.2 SD1.3 U3.76 | length 64.7
  L1 w0.178: U3.76@40.209,49.026 40.209,50.115 40.513,50.419 42.162,50.419 v1(42.937,49.645) ; v1(82.448,37.212) 83.184,37.212 83.897,36.499 88.317,36.499 SD1.3@88.624,36.806
  L6 w0.178: v1(42.937,49.645) 45.224,49.645 45.974,48.895 45.974,42.291 51.435,36.83 51.435,34.544 53.594,32.385 75.184,32.385 76.835,34.036 79.212,34.036 82.388,37.212 v1(82.448,37.212)
SD_DATA0: R33.2 SD1.7 U3.75 | length 66.9
  L1 w0.178: v1(38.1,39.497) 38.1,42.799 39.624,44.323 39.624,46.736 40.709,47.821 U3.75@40.709,49.026
  L6 w0.178: v1(38.1,39.497) 39.243,38.354 47.371,38.354 49.53,36.195 49.53,34.036 52.705,30.861 84.271,30.861 84.278,30.868 85.38,30.868 85.387,30.861 85.725,30.861 86.329,31.465 86.329,31.961 86.775,32.406 v1(88.624,32.406)
SD_DATA3: R29.2 SD1.2 U3.73 | length 66
  L1 w0.178: v1(40.386,39.497) 39.751,40.132 39.751,43.18 40.64,44.069 40.64,46.482 41.709,47.551 U3.73@41.709,49.026
  L6 w0.178: v1(40.386,39.497) 48.006,39.497 50.8,36.703 50.8,34.417 53.34,31.877 75.819,31.877 77.216,33.274 80.518,33.274 84.074,36.83 86.106,36.83 86.653,37.377 86.653,37.619 R29.2@86.994,37.96 87.048,37.906 v1(88.624,37.906)
SD_DET: R36.2 SD1.9 U3.92 | length 80.3
  L1 w0.178: U3.92@32.209,49.026 32.209,46.306 31.496,45.593 31.496,43.942 33.401,42.037 35.56,42.037 v1(37.719,44.196)
  L6 w0.178: v1(37.719,44.196) 39.318,44.196 41.148,46.026 41.148,49.276 42.291,50.419 45.466,50.419 46.482,49.403 46.482,42.545 52.07,36.957 52.07,34.798 53.975,32.893 74.041,32.893 75.946,34.798 77.597,34.798 80.391,37.592 80.391,40.259 81.773,41.641 v1(82.474,41.641)
SPI1_CS: P4.4 R60.1 U3.40 | length 38
  L1 w0.178: U3.40@43.639,31.096 44.865,31.096 45.212,30.749 45.212,25.146 46.049,24.309 46.049,23.928 v1(46.101,23.876) ; v1(55.76,3.569) 56.274,3.569 56.531,3.826 P4.4@56.531,5.588
  L6 w0.178: v1(46.101,23.876) 45.282,23.057 45.282,21.403 45.593,21.093 45.593,13.589 50.673,8.509 51.562,8.509 52.451,7.62 52.451,5.532 53.233,4.75 54.822,4.75 55.419,4.153 55.419,3.91 v1(55.76,3.569)
SPI1_MISO: P4.5 R15.1 | length 11.3
  L1 w0.178: R15.1@52.458,7.607 52.458,4.184 53.848,2.794 56.642,2.794 57.531,3.683 P4.5@57.531,5.588
SPI1_MOSI: R62.2 U3.43 | length 31.3
  L1 w0.178: U3.43@43.639,32.596 45.89,32.596 47.625,30.861 v1(47.625,25.146)
  L6 w0.178: v1(47.625,25.146) 47.625,22.352 46.778,21.505 46.778,13.674 50.8,9.652 53.455,9.652 v1(53.976,9.131)
SPI1_SCK: R61.2 U3.41 | length 31
  L1 w0.178: U3.41@43.639,31.596 45.301,31.596 45.847,31.05 45.847,25.527 46.99,24.384 46.99,23.495 v1(46.101,22.606)
  L6 w0.178: v1(46.101,22.606) 46.101,13.716 50.673,9.144 52.439,9.144 v1(53.976,7.607)
SPI3_CS: P7.4 R67.1 U3.110 | length 35.5
  L1 w0.178: v1(4.198,30.239) 3.302,31.135 3.302,35.052 4.572,36.322 6.35,36.322 8.001,37.973 8.001,45.339 10.414,47.752 19.812,47.752 20.968,46.596 U3.110@22.279,46.596 ; v1@4.255,30.239 5.585,30.239 v1(5.588,30.242)
SPI3_MISO: P7.5 U3.112 | length 32.1
  L1 w0.178: P7.5@5.588,29.242 6.89,29.242 7.239,29.591 7.239,35.687 9.271,37.719 9.271,44.831 11.176,46.736 14.478,46.736 15.618,45.596 U3.112@22.279,45.596
SPI3_MOSI: R69.2 U3.113 | length 9.1
  L1 w0.178: R69.2@13.461,45.733 14.338,45.733 14.975,45.096 U3.113@22.279,45.096
SPI3_SCK: R68.2 U3.111 | length 4.1
  L1 w0.178: R68.2@18.414,46.749 19.291,46.749 19.944,46.096 U3.111@22.279,46.096
SPI6_CS: P8.4 R70.1 U3.126 | length 40.3
  L1 w0.178: P8.4@5.588,11.779 5.586,11.777 v1(4.021,11.777) 3.556,12.243 3.556,14.986 7.112,18.542 7.112,26.67 12.446,32.004 12.446,35.56 15.482,38.596 U3.126@22.279,38.596
SPI6_MISO: P8.5 U3.127 | length 38.4
  L1 w0.178: P8.5@5.588,10.779 6.731,10.779 7.051,11.099 7.051,17.592 7.62,18.161 7.62,26.543 13.97,32.893 13.97,35.814 16.252,38.096 U3.127@22.279,38.096
SPI6_MOSI: R72.2 U3.129 | length 4.5
  L1 w0.178: R72.2@18.541,35.446 18.541,35.506 18.882,35.847 19.591,35.847 20.84,37.096 U3.129@22.279,37.096
SPI6_SCK: R71.2 U3.128 | length 4
  L1 w0.178: R71.2@18.541,36.97 18.782,37.211 20.193,37.211 20.578,37.596 U3.128@22.279,37.596
SWCLK: D7.2 J2.3 U3.109 | length 22.4
  L1 w0.178: v1(3.581,42.799) 4.136,43.354 J2.3@5.588,43.354 5.59,43.356 6.775,43.356 7.366,43.946 7.366,45.593 10.033,48.26 20.117,48.26 21.281,47.096 U3.109@22.279,47.096
SWDIO: D6.2 J2.2 U3.105 | length 27.9
  L1 w0.178: J2.2@5.588,44.354 4.507,44.354 4.064,44.797 4.064,45.822 v1(4.953,46.711) 7.595,46.711 9.652,48.768 19.685,48.768 21.717,50.8 25.133,50.8 25.709,50.224 U3.105@25.709,49.026
SWO: J2.8 U3.133 | length 18
  L1 w0.178: v1(20.491,35.096) U3.133@22.279,35.096
  L6 w0.178: v1(5.588,38.354) 10.16,38.354 10.541,37.973 17.614,37.973 v1(20.491,35.096)
TELEM: J10.1 U3.79 | length 18.1
  L1 w0.178: J10.1@28.686,59.436 28.686,53.991 31.496,51.181 37.592,51.181 38.709,50.064 U3.79@38.709,49.026
TX3_N: P1.3 R45.2 R48.1 | length 15.2
  L1 w0.254: v1(66.801,12.967) 70.498,12.967 70.866,13.335 70.866,14.224 P1.3@72.136,15.494
  L6 w0.254: v1(61.856,14.846) 61.856,14.899 62.258,15.301 63.947,15.301 64.957,14.291 66.335,14.291 67.407,13.218 67.407,12.706 67.16,12.459 66.95,12.459 66.801,12.608 v1(66.801,12.967)
TX3_P: P1.1 R46.2 R49.1 | length 16.8
  L1 w0.254: R46.2@66.817,11.443 66.817,11.368 67.443,10.742 70.465,10.742 71.695,11.972 71.695,12.513 P1.1@72.136,12.954
  L6 w0.254: v1(62.11,16.37) 62.11,15.958 62.259,15.809 64.157,15.809 65.168,14.799 66.545,14.799 67.915,13.429 67.915,12.495 67.371,11.951 66.95,11.951 66.801,11.802 v1(66.801,11.443)
TX_N: R48.2 U11.1 | length 3.6
  L1 w0.254: U11.1@57.533,16.683 57.537,16.679 58.505,16.679 59.975,15.209 60.023,15.209 60.326,14.906 R48.2@60.326,14.846
TX_P: R49.2 U11.2 | length 3.6
  L1 w0.254: U11.2@57.524,17.192 57.537,17.205 59.029,17.205 59.122,17.298 59.835,17.298 60.135,16.997 60.135,16.874 60.58,16.43 R49.2@60.58,16.37
UART4_RX: P12.2 U3.35 | length 27.8
  L1 w0.178: U3.35@41.209,27.666 41.209,26.598 41.556,26.251 42.202,26.251 v1(42.672,25.781)
  L6 w0.178: v1(41.164,5.588) 41.164,6.874 41.656,7.366 41.656,11.938 38.1,15.494 38.1,21.209 39.674,22.783 41.706,22.783 42.672,23.749 v1(42.672,25.781)
UART4_TX: P12.3 U3.34 | length 28.3
  L1 w0.178: U3.34@40.709,27.666 40.709,26.487 42.205,24.991 42.693,24.991 43.053,24.631 v1(43.053,22.86)
  L6 w0.178: v1(42.164,5.588) 42.164,12.192 38.481,15.875 38.481,20.955 39.904,22.378 42.571,22.378 v1(43.053,22.86)
USART2_RX: P13.2 U3.37 | length 32.8
  L1 w0.178: U3.37@43.639,29.596 43.639,27.862 v1(44.196,27.305) ; v1(46.228,11.049) 46.228,9.45 47.879,7.799 P13.2@47.879,5.588
  L6 w0.178: v1(44.196,27.305) 44.248,27.253 44.248,27.093 44.276,27.065 44.276,22.178 43.66,21.562 40.358,21.562 39.243,20.447 39.243,16.51 43.367,12.386 44.891,12.386 v1(46.228,11.049)
USART2_TX: P13.3 U3.36 | length 32.8
  L1 w0.178: U3.36@41.709,27.666 42.565,27.666 v1(42.926,27.305) ; v1(47.371,9.906) 48.879,8.398 P13.3@48.879,5.588
  L6 w0.178: v1(42.926,27.305) 43.796,26.435 43.796,22.46 43.321,21.985 40.146,21.985 38.862,20.701 38.862,16.256 43.307,11.811 44.196,11.811 46.101,9.906 v1(47.371,9.906)
USB_VBUS_SNS: D3.1 R1.1 R4.2 U3.101 | length 59
  L1 w0.178: U3.101@27.709,49.026 27.709,47.983 28.194,47.498 v1(28.829,47.498)
  L1 w0.254: D3.1@75.692,55.778 75.692,55.806 75.765,55.879 v1(77.457,55.879) ; R4.2@77.471,55.893 R1.1@78.987,55.893
  L6 w0.178: v1(28.829,47.498) 29.464,48.133 29.464,49.53 30.734,50.8 57.531,50.8 63.05,56.319 77.017,56.319 v1(77.457,55.879)
pads on no net: J2.1 J3.1 P1. P1.7 P3.6 SW1.5 SW2.5 U3.2 U3.7 U3.10 U3.11 U3.77 U3.80 U3.93 U3.98 U3.102 U3.116 U3.117 U3.118 U3.119 U3.122 U3.123 U3.124 U3.125 U3.132 U3.134 U3.135 U10.5 U10.8 U11.7 U11.12 U11.13 U11.18 U11.24 U11.26 U11.38 U11.39 U11.40 U11.41 U11.42 U11.46 U11.47 USB1.A8 USB1.B8

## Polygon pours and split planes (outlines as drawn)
+5V on L1 "+5V_L01_P017" (solid, pour order 17): 75.565,50.419 75.565,48.133 80.772,48.133 81.026,48.387 83.058,48.387 83.439,48.006 86.233,48.006 86.233,49.657 85.471,49.657 85.471,52.578 89.535,52.578 89.535,62.103 ccw(c86.995,62.103) 86.995,64.643 74.676,64.643 74.676,53.721 75.565,53.721
GND on L1 "GND_L01_P010" (solid, pour order 10): 44.958,16.129 44.958,17.526 44.577,17.526 42.799,19.177 42.799,21.336 41.148,21.336 41.148,19.177 39.497,19.177 39.497,18.034 42.291,18.034 43.688,16.637 43.688,16.129
GND on L1 "GND_L01_P001" (solid, pour order 1): 34.29,20.828 35.306,20.828 35.306,23.114 36.195,24.003 36.449,24.003 36.449,24.816 35.763,24.816 35.763,24.384 34.874,23.495 32.842,23.495 32.842,22.276
NetC4_1 on L1 "NETC4_1_L01_P003" (solid, pour order 3): 75.692,47.752 77.597,47.752 77.597,44.704 76.581,44.704 76.581,46.736 75.692,46.736
NetC7_1 on L1 "NETC7_1_L01_P005" (solid, pour order 5): 71.882,50.8 68.58,50.8 68.58,53.848 71.247,53.848 71.247,51.689 71.882,51.689
NetC12_2 on L1 "NETC12_2_L01_P006" (solid, pour order 6): 71.882,49.403 68.453,49.403 68.453,50.546 71.882,50.546
NetR6_2 on L1 "NETR6_2_L01_P007" (solid, pour order 7): 75.692,50.8 77.216,50.8 77.216,53.467 75.692,53.467
NetC4_2 on L1 "NETC4_2_L01_P008" (solid, pour order 8): 72.009,46.101 72.009,47.625 67.691,47.625 67.691,48.514 59.436,48.514 59.436,43.942 69.215,43.942 69.215,46.101
+3.3V on L1 "+3.3V_L01_P009" (solid, pour order 9): 71.755,35.306 71.755,45.72 69.596,45.72 69.596,43.561 59.436,43.561 59.436,35.306
CGND on L6 "CGND_L06_P011" (solid, pour order 11): 68.707,27.178 88.646,27.178 88.646,9.271 68.707,9.271
GND on L2 "GND_L02_P014" (solid, pour order 14): 0.127,65.024 90.043,65.024 90.043,0 0.127,0
+3.3V on L3 "+3.3V_L03_P018" (solid, pour order 18): 0.127,65.024 90.043,65.024 90.043,0 0.127,0
GND on L5 "GND_L05_P019" (solid, pour order 19): 0.127,65.024 90.043,65.024 90.043,0 0.127,0
GND on L4 "GND_L04_P020" (solid, pour order 20): 0.127,65.024 90.043,65.024 90.043,0 0.127,0

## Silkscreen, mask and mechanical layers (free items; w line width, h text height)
Top Overlay:
  lines w0.381: 56.642,32.766 58.293,32.893 58.42,35.306 59.944,34.29 61.595,35.052 61.976,34.036 64.262,35.306 65.532,34.036 67.056,35.433 67.056,33.909 69.215,35.052 69.596,34.036 71.628,34.925 71.755,33.909 73.787,34.671 73.406,32.004 75.819,31.623 75.184,30.734 76.2,28.829 75.438,28.829 74.549,27.432 72.517,28.448 72.263,27.432 70.485,28.194 68.199,27.559 68.199,28.702 66.167,26.67 65.405,28.194 61.849,26.67 61.595,28.194 59.563,26.924 58.928,28.067 56.896,28.194 57.277,31.115 56.642,32.766
  text "OUT" at 70.968,63.997 h1.02
  text "IN" at 73.889,63.983 h1.02
  text "USB-C" at 83.795,63.489 h1.02
  text "PDB GPIO" at 70.99,61.224 h1.02
  text "3.3V" at 70.714,58.917 h1.02
  text "DSHOT IN" at 33.325,58.866 h1.02
  text "MAG OUT" at 7.544,57.85 h1.02
  text "GPS OUT" at 12.243,57.85 h1.02
  text "PDB UART IN" at 49.2,57.723 h1.02
  text "PDB UART" at 56.888,57.716 h1.02
  text "I2C4" at 19.355,57.596 h1.02
  text "ESC GPIO" at 25.578,57.469 h1.02
  text "OUTPUT" at 57.328,57.088 h1.02
  text "&TELEM" at 26.213,56.834 h1.02
  text "GPS IN" at 7.301,53.264 h1.02 r90
  text "MAG IN" at 7.301,48.692 h1.02 r90
  text "+3.3V" at 49.124,46.979 h1.02
  text "+5V" at 50.775,46.089 h1.02
  text "PG3" at 50.775,45.074 h1.02
  text "PG4" at 50.775,44.058 h1.02
  text "PG5" at 50.775,43.042 h1.02
  text "+5V CONN" at 85.192,42.915 h1.02
  text "PG6" at 50.775,42.026 h1.02
  text "PF13" at 50.267,41.009 h1.02
  text "PB2" at 50.775,39.98 h1.02
  text "PB1" at 50.775,38.964 h1.02
  text "PROGRAM / JTAG" at 7.466,38.278 h1.02 r90
  text "PB0" at 50.775,38.088 h1.02
  text "GND" at 50.775,37.073 h1.02
  text "GND" at 50.775,36.057 h1.02
  text "HUMAN IN" at 59.03,31.717 h3.81
  text "SPI3" at 7.428,29.642 h1.02 r90
  text "LOOP - HITL" at 58.141,28.955 h3.81
  text "SD CARD" at 85.446,28.437 h1.02
  text "3.3V" at 9.119,22.341 h1.02
  text "5V" at 10.897,21.324 h1.02
  text "PF2" at 10.389,20.422 h1.02
  text "CAN" at 7.428,20.244 h1.02 r90
  text "PF3" at 10.389,19.419 h1.02
  text "PF4" at 10.389,18.39 h1.02
  text "PF5" at 10.389,17.387 h1.02
  text "NRST" at 32.652,17.372 h1.02 r90
  text "PF10" at 9.881,16.371 h1.02
  text "PC1" at 10.389,15.356 h1.02
  text "PC2_C" at 9.246,14.34 h1.02
  text "PC3_P" at 9.246,13.324 h1.02
  text "GND" at 10.262,12.435 h1.02
  text "GND" at 10.262,11.546 h1.02
  text "BOOT0" at 36.676,11.417 h1.02
  text "SPI6" at 7.428,11.1 h1.02 r90
  text "ETHERNET" at 84.684,7.976 h1.02
  text "I2C1" at 17.069,6.923 h1.02
  text "RF OUT" at 33.706,6.923 h1.02
  text "UART4" at 41.072,6.923 h1.02
  text "USART2" at 46.279,6.923 h1.02
  text "SPI1" at 58.471,6.923 h1.02
  text "RF IN" at 24.308,6.909 h1.02
  text "FMU UART" at 8.687,6.796 h1.02
  text "SCHEMATIC AND LAYOUT:" at 69.571,5.337 h1.78
  text "BY: T STOLPE" at 70.968,3.94 h1.78
  text "CHK: J TOLDEN" at 70.968,2.67 h1.78
  text "REV: -" at 70.968,1.4 h1.78
  text "5V" at 83.248,1.067 h1.02 r90
  text "3.3V" at 87.819,0.94 h1.02 r90
Mechanical 1:
  the board outline again, w0.381
Dimensions:
  text "LAYER 1:  SIGNAL" at -68.795,51.367 h3.05
  text "LAYER 2:  GND" at -68.795,46.199 h3.05
  text "LAYER 3:  SIGNAL" at -68.819,41.275 h3.05
  text "LAYER 4:  POWER" at -68.566,36.449 h3.05
  text "LAYER 5:  GND" at -68.568,31.496 h3.05
  text "LAYER 6:  SIGNAL" at -68.438,26.416 h3.05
